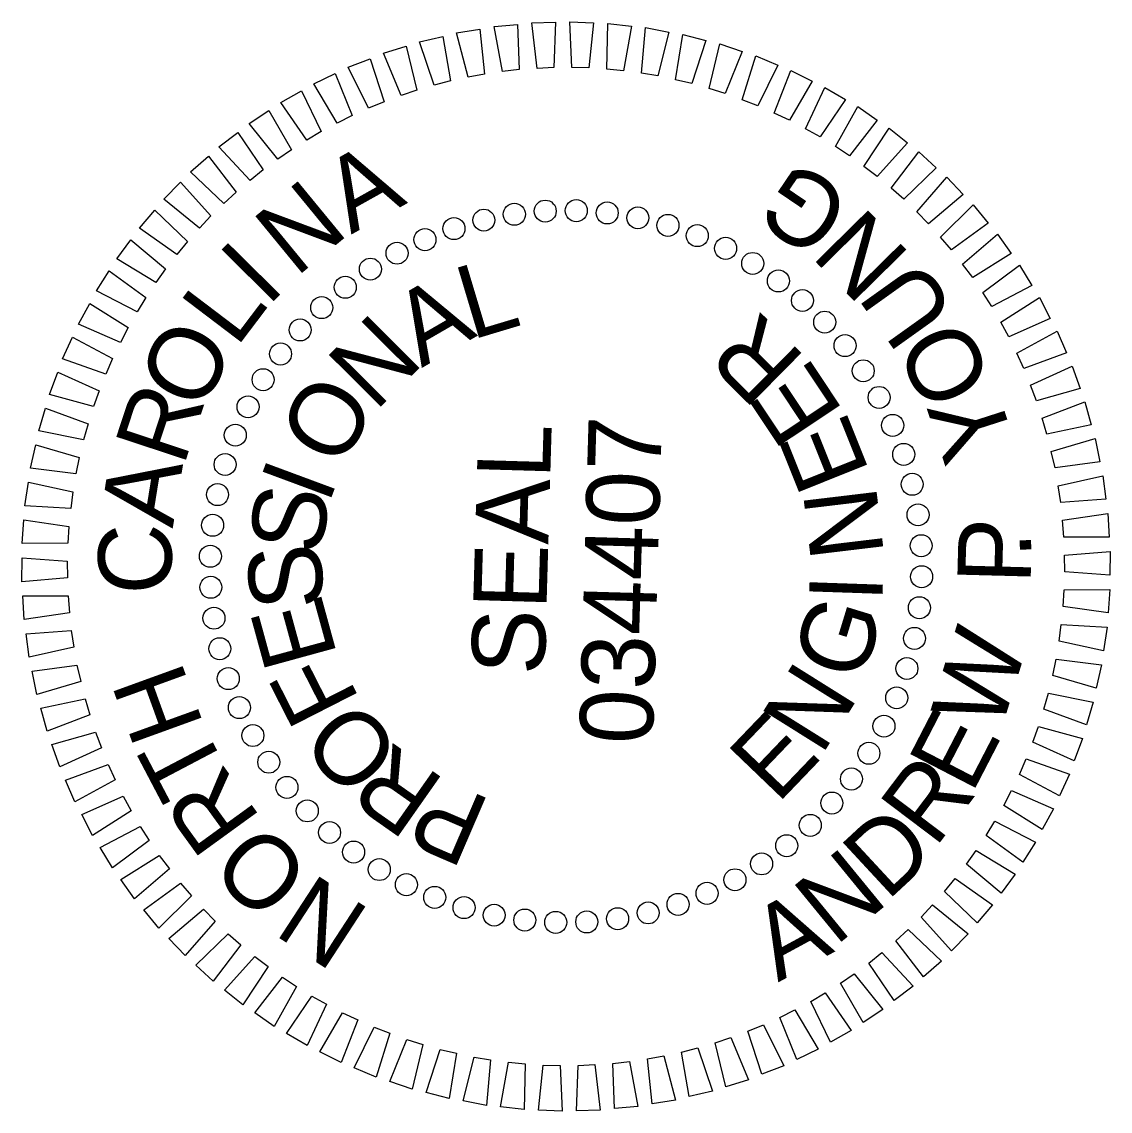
# Model space of a CAD drawing. Extents: x 2098230 to 2099272, y 990384 to 991889.
# Drawn here: x 2098284.8 to 2098360.4, y 991714.1 to 991789.8 of the extents above; entities that cross this region are included whole.
import ezdxf

# ---------------------------------------------------------------- set-up
doc = ezdxf.new("R2010")
doc.units = 0
doc.layers.add('Sheet PE Seal Cell', color=7, linetype='Continuous')

msp = doc.modelspace()

# ---------------------------------------------------------------- linework, layer by layer
at = {"layer": 'Sheet PE Seal Cell'}
for points in [[(2098315.792, 991785.965), (2098314.984, 991789.044), (2098316.611, 991789.311), (2098316.937, 991786.181)], [(2098318.18, 991786.356), (2098317.589, 991789.484), (2098319.23, 991789.637), (2098319.337, 991786.493)], [(2098320.59, 991786.58), (2098320.218, 991789.742), (2098321.867, 991789.78), (2098321.754, 991786.636)], [(2098323.009, 991786.636), (2098322.859, 991789.816), (2098324.506, 991789.739), (2098324.174, 991786.61)], [(2098325.427, 991786.522), (2098325.499, 991789.705), (2098327.137, 991789.513), (2098326.587, 991786.415)], [(2098327.831, 991786.24), (2098328.125, 991789.41), (2098329.745, 991789.105), (2098328.981, 991786.052)], [(2098313.436, 991785.407), (2098312.416, 991788.423), (2098314.02, 991788.803), (2098314.564, 991785.704)], [(2098330.209, 991785.791), (2098330.723, 991788.933), (2098332.318, 991788.515), (2098331.343, 991785.523)], [(2098311.126, 991784.687), (2098309.897, 991787.624), (2098311.471, 991788.115), (2098312.23, 991785.061)], [(2098332.55, 991785.177), (2098333.282, 991788.276), (2098334.844, 991787.748), (2098333.663, 991784.831)], [(2098308.871, 991783.808), (2098307.441, 991786.652), (2098308.977, 991787.251), (2098309.946, 991784.258)], [(2098334.843, 991784.402), (2098335.789, 991787.441), (2098337.31, 991786.806), (2098335.928, 991783.979)], [(2098306.683, 991782.773), (2098305.058, 991785.511), (2098306.548, 991786.216), (2098307.724, 991783.297)], [(2098337.075, 991783.468), (2098338.232, 991786.434), (2098339.705, 991785.694), (2098338.129, 991782.971)], [(2098304.573, 991781.588), (2098302.76, 991784.206), (2098304.198, 991785.013), (2098305.575, 991782.184)], [(2098339.238, 991782.381), (2098340.598, 991785.26), (2098342.016, 991784.418), (2098340.254, 991781.811)], [(2098341.319, 991781.146), (2098342.877, 991783.922), (2098344.233, 991782.984), (2098342.293, 991780.507)], [(2098302.55, 991780.259), (2098300.56, 991782.744), (2098301.937, 991783.649), (2098303.508, 991780.923)], [(2098343.309, 991779.769), (2098345.057, 991782.43), (2098346.344, 991781.399), (2098344.236, 991779.063)], [(2098300.625, 991778.792), (2098298.466, 991781.132), (2098299.777, 991782.131), (2098301.535, 991779.521)], [(2098298.807, 991777.195), (2098296.49, 991779.378), (2098297.729, 991780.467), (2098299.664, 991777.985)], [(2098345.198, 991778.256), (2098347.127, 991780.788), (2098348.339, 991779.671), (2098346.074, 991777.487)], [(2098297.105, 991775.474), (2098294.642, 991777.49), (2098295.801, 991778.663), (2098297.904, 991776.322)], [(2098346.977, 991776.615), (2098349.078, 991779.007), (2098350.209, 991777.807), (2098347.797, 991775.787)], [(2098348.637, 991774.854), (2098350.9, 991777.093), (2098351.945, 991775.818), (2098349.397, 991773.971)], [(2098295.528, 991773.639), (2098292.929, 991775.478), (2098294.004, 991776.729), (2098296.265, 991774.541)], [(2098350.17, 991772.981), (2098352.584, 991775.057), (2098353.537, 991773.712), (2098350.867, 991772.047)], [(2098294.082, 991771.698), (2098291.361, 991773.352), (2098292.346, 991774.674), (2098294.755, 991772.649)], [(2098292.774, 991769.661), (2098289.945, 991771.121), (2098290.836, 991772.509), (2098293.379, 991770.657)], [(2098351.569, 991771.006), (2098354.122, 991772.909), (2098354.979, 991771.5), (2098352.199, 991770.026)], [(2098291.613, 991767.538), (2098288.689, 991768.797), (2098289.48, 991770.244), (2098292.147, 991768.574)], [(2098352.827, 991768.938), (2098355.506, 991770.658), (2098356.263, 991769.194), (2098353.387, 991767.916)], [(2098353.937, 991766.788), (2098356.73, 991768.317), (2098357.383, 991766.803), (2098354.425, 991765.729)], [(2098290.602, 991765.339), (2098287.597, 991766.391), (2098288.285, 991767.89), (2098291.062, 991766.41)], [(2098354.895, 991764.565), (2098357.787, 991765.896), (2098358.333, 991764.34), (2098355.307, 991763.475)], [(2098289.747, 991763.075), (2098286.676, 991763.915), (2098287.258, 991765.458), (2098290.131, 991764.175)], [(2098355.695, 991762.281), (2098358.674, 991763.407), (2098359.109, 991761.817), (2098356.031, 991761.165)], [(2098289.051, 991760.757), (2098285.93, 991761.381), (2098286.403, 991762.96), (2098289.359, 991761.881)], [(2098288.52, 991758.396), (2098285.362, 991758.8), (2098285.724, 991760.409), (2098288.748, 991759.539)], [(2098356.335, 991759.947), (2098359.384, 991760.862), (2098359.707, 991759.245), (2098356.591, 991758.81)], [(2098356.809, 991757.574), (2098359.915, 991758.274), (2098360.125, 991756.638), (2098356.986, 991756.422)], [(2098288.154, 991756.003), (2098284.976, 991756.187), (2098285.225, 991757.816), (2098288.302, 991757.159)], [(2098287.956, 991753.591), (2098284.773, 991753.552), (2098284.907, 991755.196), (2098288.023, 991754.755)], [(2098357.117, 991755.173), (2098360.264, 991755.655), (2098360.36, 991754.009), (2098357.213, 991754.012)], [(2098357.257, 991752.757), (2098360.43, 991753.018), (2098360.41, 991751.369), (2098357.272, 991751.592)], [(2098287.927, 991751.171), (2098284.754, 991750.91), (2098284.774, 991752.559), (2098287.913, 991752.337)], [(2098288.067, 991748.755), (2098284.92, 991748.273), (2098284.824, 991749.919), (2098287.971, 991749.916)], [(2098357.228, 991750.337), (2098360.411, 991750.376), (2098360.277, 991748.733), (2098357.161, 991749.174)], [(2098288.375, 991746.355), (2098285.269, 991745.655), (2098285.059, 991747.29), (2098288.198, 991747.506)], [(2098357.03, 991747.925), (2098360.208, 991747.742), (2098359.959, 991746.112), (2098356.882, 991746.769)], [(2098356.664, 991745.533), (2098359.822, 991745.128), (2098359.46, 991743.52), (2098356.436, 991744.39)], [(2098288.85, 991743.981), (2098285.8, 991743.066), (2098285.477, 991744.683), (2098288.593, 991745.118)], [(2098356.133, 991743.171), (2098359.254, 991742.548), (2098358.781, 991740.968), (2098355.825, 991742.047)], [(2098289.489, 991741.647), (2098286.511, 991740.522), (2098286.075, 991742.112), (2098289.153, 991742.763)], [(2098355.438, 991740.853), (2098358.508, 991740.013), (2098357.926, 991738.471), (2098355.053, 991739.753)], [(2098290.289, 991739.363), (2098287.397, 991738.033), (2098286.851, 991739.588), (2098289.877, 991740.453)], [(2098354.582, 991738.589), (2098357.587, 991737.537), (2098356.899, 991736.039), (2098354.122, 991737.519)], [(2098291.247, 991737.14), (2098288.454, 991735.611), (2098287.801, 991737.125), (2098290.759, 991738.199)], [(2098353.572, 991736.39), (2098356.496, 991735.131), (2098355.704, 991733.684), (2098353.037, 991735.354)], [(2098292.357, 991734.99), (2098289.678, 991733.27), (2098288.921, 991734.735), (2098291.797, 991736.012)], [(2098293.615, 991732.922), (2098291.062, 991731.019), (2098290.205, 991732.428), (2098292.985, 991733.903)], [(2098352.41, 991734.267), (2098355.239, 991732.807), (2098354.349, 991731.419), (2098351.805, 991733.271)], [(2098295.014, 991730.947), (2098292.6, 991728.871), (2098291.647, 991730.216), (2098294.317, 991731.881)], [(2098351.103, 991732.23), (2098353.823, 991730.576), (2098352.838, 991729.254), (2098350.429, 991731.279)], [(2098349.657, 991730.289), (2098352.255, 991728.45), (2098351.18, 991727.199), (2098348.919, 991729.387)], [(2098296.547, 991729.075), (2098294.284, 991726.835), (2098293.239, 991728.111), (2098295.787, 991729.958)], [(2098298.207, 991727.314), (2098296.106, 991724.922), (2098294.975, 991726.121), (2098297.387, 991728.142)], [(2098348.079, 991728.454), (2098350.542, 991726.438), (2098349.383, 991725.266), (2098347.28, 991727.606)], [(2098299.986, 991725.673), (2098298.057, 991723.14), (2098296.845, 991724.258), (2098299.11, 991726.441)], [(2098346.377, 991726.734), (2098348.694, 991724.55), (2098347.455, 991723.462), (2098345.52, 991725.943)], [(2098301.875, 991724.16), (2098300.127, 991721.499), (2098298.84, 991722.529), (2098300.948, 991724.866)], [(2098344.559, 991725.136), (2098346.718, 991722.796), (2098345.407, 991721.797), (2098343.649, 991724.407)], [(2098303.865, 991722.782), (2098302.307, 991720.006), (2098300.951, 991720.944), (2098302.891, 991723.422)], [(2098342.634, 991723.669), (2098344.624, 991721.185), (2098343.247, 991720.279), (2098341.676, 991723.005)], [(2098305.946, 991721.547), (2098304.586, 991718.669), (2098303.168, 991719.51), (2098304.93, 991722.117)], [(2098340.611, 991722.34), (2098342.424, 991719.723), (2098340.986, 991718.915), (2098339.609, 991721.745)], [(2098338.501, 991721.155), (2098340.126, 991718.418), (2098338.636, 991717.713), (2098337.46, 991720.631)], [(2098308.109, 991720.46), (2098306.952, 991717.494), (2098305.479, 991718.234), (2098307.055, 991720.958)], [(2098310.342, 991719.526), (2098309.395, 991716.487), (2098307.874, 991717.123), (2098309.256, 991719.949)], [(2098336.313, 991720.121), (2098337.743, 991717.276), (2098336.208, 991716.677), (2098335.238, 991719.67)], [(2098312.634, 991718.751), (2098311.902, 991715.653), (2098310.34, 991716.181), (2098311.521, 991719.097)], [(2098334.058, 991719.241), (2098335.287, 991716.304), (2098333.713, 991715.813), (2098332.954, 991718.867)], [(2098314.975, 991718.137), (2098314.461, 991714.995), (2098312.866, 991715.413), (2098313.841, 991718.405)], [(2098331.748, 991718.521), (2098332.768, 991715.505), (2098331.164, 991715.125), (2098330.62, 991718.225)], [(2098317.353, 991717.688), (2098317.059, 991714.518), (2098315.439, 991714.824), (2098316.203, 991717.876)], [(2098319.757, 991717.406), (2098319.685, 991714.224), (2098318.047, 991714.415), (2098318.597, 991717.514)], [(2098322.175, 991717.293), (2098322.325, 991714.113), (2098320.678, 991714.19), (2098321.01, 991717.319)], [(2098324.594, 991717.348), (2098324.966, 991714.186), (2098323.317, 991714.148), (2098323.43, 991717.293)], [(2098327.004, 991717.572), (2098327.595, 991714.444), (2098325.954, 991714.291), (2098325.847, 991717.436)], [(2098329.392, 991717.964), (2098330.2, 991714.884), (2098328.573, 991714.617), (2098328.247, 991717.747)]]:
    msp.add_lwpolyline(points, close=True, dxfattribs=at)
for centre in [(2098319, 991776.439), (2098321.147, 991776.659), (2098323.305, 991776.691), (2098325.457, 991776.535), (2098316.88, 991776.033), (2098327.588, 991776.192), (2098329.68, 991775.664), (2098314.804, 991775.444), (2098331.719, 991774.956), (2098312.788, 991774.676), (2098333.688, 991774.073), (2098310.845, 991773.735), (2098308.993, 991772.628), (2098335.573, 991773.022), (2098337.359, 991771.811), (2098307.244, 991771.364), (2098339.032, 991770.448), (2098305.611, 991769.953), (2098340.581, 991768.945), (2098304.108, 991768.404), (2098341.992, 991767.313), (2098302.745, 991766.731), (2098301.534, 991764.945), (2098343.256, 991765.563), (2098344.363, 991763.711), (2098300.483, 991763.06), (2098345.304, 991761.769), (2098299.6, 991761.091), (2098346.072, 991759.752), (2098298.892, 991759.052), (2098346.661, 991757.676), (2098298.364, 991756.96), (2098347.067, 991755.556), (2098298.021, 991754.829), (2098347.287, 991753.41), (2098297.865, 991752.677), (2098297.897, 991750.519), (2098347.319, 991751.252), (2098347.163, 991749.099), (2098298.117, 991748.372), (2098346.82, 991746.969), (2098298.523, 991746.253), (2098346.292, 991744.876), (2098299.112, 991744.176), (2098345.584, 991742.837), (2098299.881, 991742.16), (2098344.701, 991740.868), (2098300.821, 991740.218), (2098343.65, 991738.984), (2098301.928, 991738.365), (2098342.439, 991737.198), (2098303.192, 991736.616), (2098341.076, 991735.524), (2098304.603, 991734.983), (2098339.573, 991733.976), (2098306.152, 991733.48), (2098337.941, 991732.564), (2098307.825, 991732.118), (2098309.611, 991730.906), (2098336.191, 991731.3), (2098334.339, 991730.194), (2098311.496, 991729.855), (2098313.465, 991728.972), (2098332.396, 991729.253), (2098315.504, 991728.264), (2098328.304, 991727.895), (2098330.38, 991728.485), (2098317.597, 991727.736), (2098319.727, 991727.393), (2098321.88, 991727.237), (2098324.037, 991727.269), (2098326.184, 991727.489)]:
    msp.add_circle(centre, 0.765, dxfattribs=at)

# ---------------------------------------------------------------- texts
for s, height, rotation, p in [('A', 5.101, 29.20951, (2098307.655, 991775.022)), ('G', 5.101, 145.88414, (2098342.722, 991777.416)), ('N', 5.101, 39.41994, (2098303.804, 991772.009)), ('N', 5.101, 134.55844, (2098346.652, 991773.59)), ('I', 5.1, 45.35991, (2098301.831, 991769.957)), ('L', 5.1, 16.7052, (2098316.007, 991767.694)), ('U', 5.1, 125.51095, (2098349.825, 991769.607)), ('L', 5.101, 52.82504, (2098299.669, 991767.107)), ('A', 5.1, 30.04109, (2098312.557, 991765.751)), ('R', 5.101, 135.39251, (2098339.354, 991766.416)), ('N', 5.101, 45.09115, (2098309.321, 991762.673)), ('O', 5.1, 63.55021, (2098297.251, 991762.577)), ('O', 5.101, 117.3023, (2098352.395, 991764.79)), ('E', 5.1, 123.63027, (2098341.948, 991762.695)), ('R', 5.1, 71.75886, (2098295.996, 991758.85)), ('O', 5.101, 60.89992, (2098306.905, 991758.652)), ('Y', 5.1, 107.79726, (2098353.872, 991760.316)), ('034407', 5.1005, 88.34956, (2098328.613, 991739.568)), ('E', 5.101, 111.86803, (2098343.729, 991758.524)), ('SEAL', 5.1005, 88.34956, (2098321.098, 991744.38)), ('A', 5.101, 80.80635, (2098295.244, 991754.582)), ('I', 5.1, 69.65537, (2098306.07, 991756.186)), ('S', 5.101, 81.61432, (2098305.554, 991752.671)), ('N', 5.1, 96.81797, (2098344.708, 991752.81)), ('C', 5.1, 90.31139, (2098295.187, 991750.03)), ('P', 5.1, 88.50697, (2098354.889, 991750.709)), ('.', 5.1, 91.82798, (2098354.964, 991752.534)), ('S', 5.101, 93.57327, (2098305.777, 991749.125)), ('I', 5.101, 88.06253, (2098344.579, 991749.434)), ('E', 5.101, 105.33552, (2098306.709, 991745.757)), ('G', 5.1, 73.01247, (2098343.168, 991743.812)), ('W', 5.101, 72.81549, (2098352.795, 991740.416)), ('H', 5.101, 109.9506, (2098297.431, 991740.932)), ('F', 5.1, 117.01346, (2098308.294, 991742.671)), ('N', 5.101, 57.96242, (2098340.345, 991738.749)), ('O', 5.101, 132.82224, (2098311.366, 991739.127)), ('E', 5.101, 46.20018, (2098337.278, 991735.407)), ('E', 5.101, 62.654, (2098350.801, 991736.089)), ('T', 5.1, 117.73983, (2098299.159, 991737.624)), ('R', 5.101, 144.92169, (2098314.307, 991737.059)), ('R', 5.101, 52.95025, (2098348.251, 991732.338)), ('R', 5.101, 125.94848, (2098301.446, 991734.425)), ('P', 5.101, 156.68394, (2098317.519, 991735.683)), ('D', 5.1, 42.83529, (2098344.903, 991728.658)), ('O', 5.101, 136.67365, (2098305.08, 991730.796)), ('N', 5.101, 39.3357, (2098341.311, 991725.533)), ('N', 5.101, 146.88408, (2098309.109, 991728.027)), ('A', 5.1, 28.46341, (2098337.338, 991723.057))]:
    msp.add_text(s, height=height, rotation=rotation, dxfattribs=at).set_placement(p)

doc.saveas('drawing.dxf')
